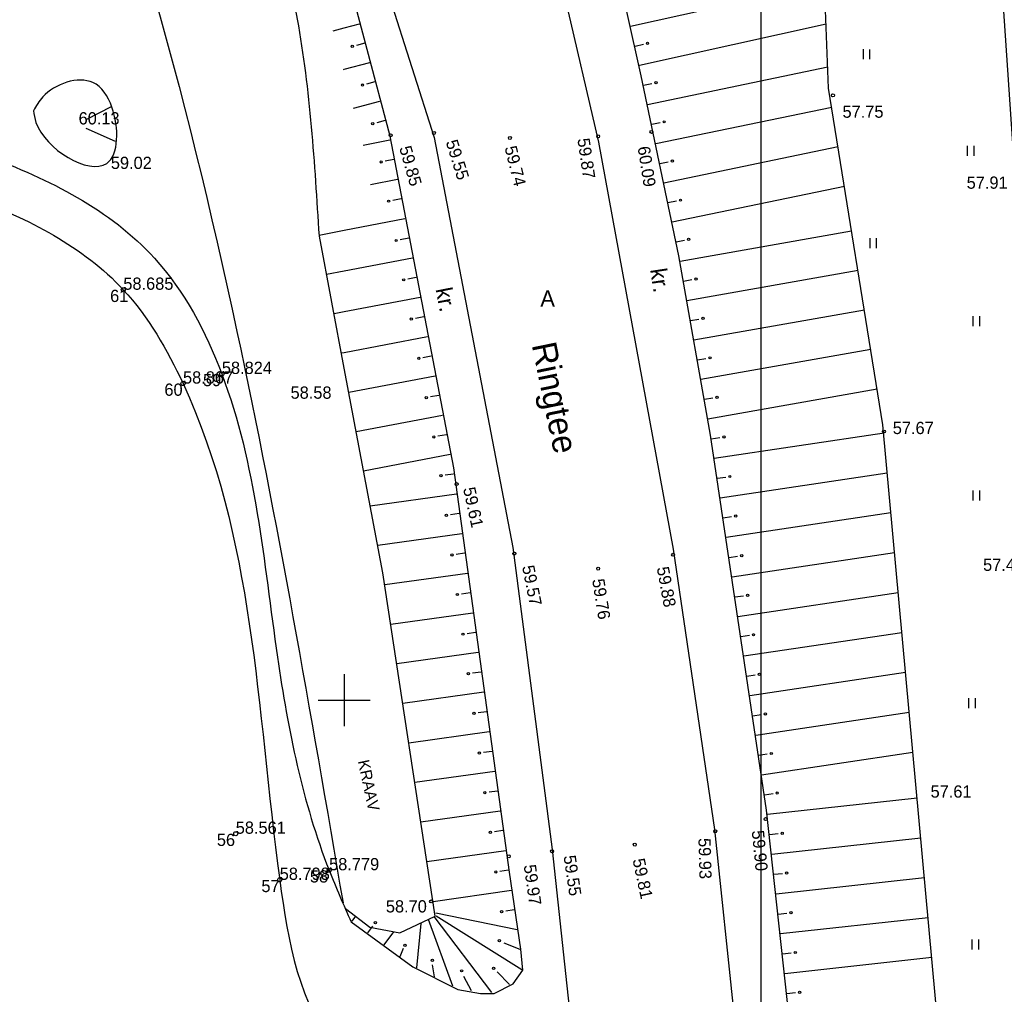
# Model space of a CAD drawing. Extents: x 9156 to 9809, y 2728 to 4000.
# Drawn here: x 9230.1 to 9290.4, y 3632 to 3691.7 of the extents above; entities that cross this region are included whole.
import ezdxf

# ---------------------------------------------------------------- set-up
doc = ezdxf.new("R2010")
doc.units = 0
doc.layers.add('Level 54', color=7, linetype='Continuous')
doc.layers.add('Level 63', color=7, linetype='Continuous')

msp = doc.modelspace()

# ---------------------------------------------------------------- linework, layer by layer
at = {"layer": 'Level 54'}
for p, q in [((9265.589, 3684.178), (9262.725, 3696.473)), ((9279.408, 3693.912), (9267.541, 3691.269)), ((9252.647, 3693.428), (9255.511, 3684.465)), ((9250, 3691.186), (9250.935, 3691.433)), ((9279.509, 3691.423), (9268.073, 3688.877)), ((9249.316, 3691.006), (9250, 3691.186)), ((9251.247, 3690.248), (9250.739, 3690.114)), ((9267.807, 3690.073), (9268.32, 3690.187)), ((9281.776, 3689.881), (9281.776, 3689.261)), ((9282.181, 3689.87), (9282.181, 3689.261)), ((9250, 3688.652), (9251.56, 3689.062)), ((9249.941, 3688.636), (9250, 3688.652)), ((9279.616, 3688.771), (9268.581, 3686.479)), ((9251.872, 3687.877), (9251.363, 3687.743)), ((9268.331, 3687.679), (9268.846, 3687.786)), ((9250.565, 3686.266), (9252.184, 3686.692)), ((9234.228, 3685.586), (9235.745, 3686.368)), ((9279.858, 3686.318), (9269.079, 3684.079)), ((9252.496, 3685.507), (9251.988, 3685.373)), ((9268.83, 3685.279), (9269.345, 3685.386)), ((9234.165, 3685.037), (9235.956, 3684.256)), ((9251.149, 3684.003), (9252.793, 3684.318)), ((9255.511, 3684.465), (9260.322, 3659.355)), ((9270.172, 3659.243), (9265.589, 3684.178)), ((9280.248, 3683.896), (9269.578, 3681.679)), ((9288.165, 3683.966), (9288.165, 3683.346)), ((9288.571, 3683.954), (9288.571, 3683.346)), ((9253.024, 3683.115), (9252.507, 3683.016)), ((9269.328, 3682.879), (9269.843, 3682.986)), ((9251.61, 3681.596), (9253.255, 3681.911)), ((9280.638, 3681.473), (9270.076, 3679.279)), ((9253.485, 3680.707), (9252.969, 3680.608)), ((9269.827, 3680.479), (9270.342, 3680.586)), ((9250, 3678.792), (9253.716, 3679.504)), ((9248.459, 3678.496), (9250, 3678.792)), ((9281.078, 3678.739), (9270.564, 3676.877)), ((9250, 3670.328), (9248.471, 3678.435)), ((9253.946, 3678.3), (9253.43, 3678.201)), ((9270.325, 3678.079), (9270.84, 3678.186)), ((9282.183, 3678.307), (9282.183, 3677.687)), ((9282.588, 3678.296), (9282.588, 3677.687)), ((9250, 3676.296), (9254.177, 3677.096)), ((9248.913, 3676.088), (9250, 3676.296)), ((9254.408, 3675.893), (9253.891, 3675.794)), ((9270.778, 3675.67), (9271.296, 3675.762)), ((9281.468, 3676.319), (9270.992, 3674.464)), ((9250, 3673.8), (9254.638, 3674.689)), ((9249.368, 3673.679), (9250, 3673.8)), ((9254.869, 3673.485), (9254.353, 3673.386)), ((9271.205, 3673.257), (9271.723, 3673.348)), ((9281.858, 3673.898), (9271.419, 3672.05)), ((9288.505, 3673.534), (9288.505, 3672.914)), ((9288.91, 3673.523), (9288.91, 3672.914)), ((9250, 3671.304), (9255.1, 3672.282)), ((9249.822, 3671.27), (9250, 3671.304)), ((9255.33, 3671.078), (9254.814, 3670.979)), ((9271.633, 3670.843), (9272.15, 3670.935)), ((9282.248, 3671.478), (9271.846, 3669.636)), ((9252.363, 3657.799), (9250, 3670.328)), ((9250.277, 3668.862), (9255.561, 3669.874)), ((9255.792, 3668.671), (9255.275, 3668.572)), ((9272.06, 3668.43), (9272.578, 3668.521)), ((9282.637, 3669.058), (9272.274, 3667.223)), ((9250.731, 3666.453), (9256.022, 3667.467)), ((9256.253, 3666.263), (9255.737, 3666.164)), ((9272.481, 3666.015), (9273.001, 3666.093)), ((9283.072, 3666.36), (9272.662, 3664.803)), ((9251.185, 3664.044), (9256.484, 3665.06)), ((9256.695, 3663.853), (9256.175, 3663.781)), ((9272.844, 3663.591), (9273.364, 3663.669)), ((9283.261, 3663.91), (9273.025, 3662.379)), ((9251.588, 3661.909), (9256.863, 3662.639)), ((9288.505, 3662.852), (9288.505, 3662.232)), ((9288.91, 3662.841), (9288.91, 3662.232)), ((9257.031, 3661.425), (9256.511, 3661.353)), ((9283.486, 3661.465), (9273.388, 3659.955)), ((9273.206, 3661.167), (9273.726, 3661.244)), ((9252.043, 3659.497), (9257.199, 3660.211)), ((9257.368, 3658.997), (9256.847, 3658.925)), ((9260.322, 3659.355), (9262.728, 3640.855)), ((9272.689, 3642.079), (9270.172, 3659.243)), ((9283.71, 3659.02), (9273.75, 3657.53)), ((9273.569, 3658.742), (9274.089, 3658.82)), ((9255.572, 3636.771), (9252.363, 3657.799)), ((9252.473, 3657.082), (9257.536, 3657.783)), ((9257.704, 3656.569), (9257.183, 3656.497)), ((9283.934, 3656.575), (9274.113, 3655.106)), ((9273.931, 3656.318), (9274.451, 3656.396)), ((9252.843, 3654.659), (9257.872, 3655.355)), ((9258.04, 3654.141), (9257.519, 3654.069)), ((9284.159, 3654.13), (9274.475, 3652.682)), ((9274.294, 3653.894), (9274.814, 3653.972)), ((9253.212, 3652.235), (9258.208, 3652.927)), ((9258.376, 3651.713), (9257.855, 3651.641)), ((9284.383, 3651.686), (9274.838, 3650.258)), ((9250, 3651.593), (9250, 3648.407)), ((9250, 3651.593), (9250, 3648.407)), ((9250, 3651.593), (9250, 3648.407)), ((9250, 3651.593), (9250, 3648.407)), ((9250, 3651.25), (9250, 3648.75)), ((9274.657, 3651.47), (9275.177, 3651.548)), ((9253.582, 3649.812), (9258.544, 3650.499)), ((9248.407, 3650), (9250, 3650)), ((9248.407, 3650), (9250, 3650)), ((9248.75, 3650), (9251.25, 3650)), ((9250, 3650), (9251.593, 3650)), ((9250, 3650), (9251.593, 3650)), ((9288.233, 3650.122), (9288.233, 3649.502)), ((9288.638, 3650.111), (9288.638, 3649.502)), ((9258.712, 3649.285), (9258.191, 3649.213)), ((9284.608, 3649.241), (9275.2, 3647.834)), ((9275.019, 3649.046), (9275.539, 3649.124)), ((9253.952, 3647.389), (9258.88, 3648.071)), ((9259.048, 3646.857), (9258.527, 3646.785)), ((9284.832, 3646.796), (9275.563, 3645.41)), ((9275.382, 3646.622), (9275.902, 3646.699)), ((9254.321, 3644.965), (9259.216, 3645.643)), ((9259.384, 3644.429), (9258.863, 3644.357)), ((9275.744, 3644.197), (9276.264, 3644.275)), ((9285.09, 3643.986), (9275.914, 3642.984)), ((9254.691, 3642.542), (9259.552, 3643.215)), ((9259.72, 3642.001), (9259.199, 3641.929)), ((9278.071, 3591.482), (9272.689, 3642.079)), ((9276.047, 3641.766), (9276.57, 3641.823)), ((9285.314, 3641.544), (9276.18, 3640.547)), ((9255.061, 3640.119), (9259.888, 3640.787)), ((9262.728, 3640.855), (9267.882, 3592.77)), ((9260.056, 3639.573), (9259.535, 3639.501)), ((9276.313, 3639.329), (9276.836, 3639.386)), ((9285.538, 3639.103), (9276.446, 3638.111)), ((9255.436, 3637.66), (9260.232, 3638.36)), ((9250.072, 3637.23), (9251.561, 3636.081)), ((9260.409, 3637.147), (9259.889, 3637.071)), ((9250.676, 3636.764), (9250.45, 3636.455)), ((9253.395, 3635.736), (9255.572, 3636.771)), ((9255.146, 3636.572), (9256.621, 3632.498)), ((9255.49, 3636.744), (9259.01, 3632.088)), ((9255.605, 3636.974), (9260.586, 3635.935)), ((9255.633, 3636.773), (9260.873, 3633.501)), ((9276.579, 3636.892), (9277.102, 3636.949)), ((9285.763, 3636.662), (9276.712, 3635.674)), ((9251.44, 3635.732), (9251.75, 3636.157)), ((9251.561, 3636.081), (9253.395, 3635.736)), ((9254.688, 3636.313), (9254.43, 3633.597)), ((9253.012, 3635.808), (9252.43, 3635.01)), ((9288.436, 3635.342), (9288.436, 3634.722)), ((9288.842, 3635.331), (9288.842, 3634.722)), ((9253.42, 3634.288), (9253.628, 3634.791)), ((9260.762, 3634.722), (9259.787, 3635.107)), ((9276.845, 3634.456), (9277.368, 3634.513)), ((9285.987, 3634.221), (9276.978, 3633.237)), ((9255.525, 3633.048), (9255.404, 3633.785)), ((9257.792, 3632.182), (9257.323, 3633.067)), ((9260.121, 3632.571), (9259.357, 3633.354)), ((9277.111, 3632.019), (9277.634, 3632.076))]:
    msp.add_line(p, q, dxfattribs=at)
for points in [[(9250, 3738.614), (9253.398, 3731.987), (9257.522, 3722.336), (9261.761, 3711.307), (9265.539, 3700.09), (9268.174, 3688.256), (9270.465, 3677.226), (9272.41, 3666.239), (9275.847, 3643.259), (9278.136, 3622.295), (9281, 3595.752), (9283.628, 3570.325), (9285.461, 3545.046), (9287.293, 3525.67), (9289.24, 3507.056), (9289.458, 3500)], [(9289.521, 3722.865), (9289.636, 3711.949), (9290.094, 3696.436), (9293.302, 3649.242), (9295.59, 3619.198), (9296.851, 3602.192), (9300.163, 3556.342), (9301.424, 3542.094), (9302.684, 3538.991), (9304.632, 3528.075), (9306.915, 3513.758), (9308.634, 3504.221), (9309.025, 3500)], [(9298.789, 3500), (9298.217, 3515.72), (9298.103, 3526.407), (9296.155, 3540.196), (9294.785, 3549.211), (9292.952, 3569.435), (9290.202, 3589.084), (9286.767, 3619.468), (9285.736, 3621.307), (9285.048, 3622.915), (9284.705, 3624.754), (9285.736, 3627.512), (9286.423, 3629.465), (9282.989, 3666.871), (9279.667, 3687.502), (9279.324, 3696.006), (9278.522, 3701.406), (9275.886, 3702.9), (9273.137, 3704.049)], [(9250.418, 3636.41), (9254.202, 3633.65), (9256.963, 3632.265), (9258.351, 3632.033), (9259.17, 3632.033), (9260.34, 3632.62), (9260.932, 3633.452), (9260.816, 3634.737), (9260.128, 3639.45), (9256.699, 3664.227), (9252.804, 3684.55), (9250, 3695.198)]]:
    msp.add_lwpolyline(points, dxfattribs=at)
for centre, radius in [((9268.571, 3690.236), 0.0683), ((9250.49, 3690.056), 0.0683), ((9269.098, 3687.83), 0.0683), ((9251.114, 3687.685), 0.0683), ((9279.936, 3687.055), 0.0909), ((9251.739, 3685.315), 0.0683), ((9269.596, 3685.43), 0.0683), ((9255.489, 3684.748), 0.0909), ((9268.813, 3684.816), 0.0909), ((9252.838, 3684.612), 0.0909), ((9260.146, 3684.441), 0.0909), ((9265.55, 3684.544), 0.0909), ((9252.255, 3682.975), 0.0683), ((9270.095, 3683.031), 0.0683), ((9252.716, 3680.568), 0.0683), ((9270.593, 3680.631), 0.0683), ((9253.178, 3678.16), 0.0683), ((9271.092, 3678.231), 0.0683), ((9253.639, 3675.753), 0.0683), ((9271.549, 3675.799), 0.0683), ((9236.462, 3675.142), 0.125), ((9254.1, 3673.346), 0.0683), ((9271.976, 3673.386), 0.0683), ((9254.562, 3670.938), 0.0683), ((9272.403, 3670.972), 0.0683), ((9242.498, 3669.984), 0.125), ((9240.118, 3669.396), 0.125), ((9255.023, 3668.531), 0.0683), ((9272.831, 3668.558), 0.0683), ((9255.484, 3666.124), 0.0683), ((9273.255, 3666.123), 0.0683), ((9283.056, 3666.453), 0.0909), ((9255.92, 3663.753), 0.0683), ((9273.617, 3663.699), 0.0683), ((9256.882, 3663.237), 0.0909), ((9256.256, 3661.325), 0.0683), ((9273.98, 3661.275), 0.0683), ((9256.593, 3658.897), 0.0683), ((9260.417, 3658.976), 0.0909), ((9270.138, 3658.908), 0.0909), ((9274.343, 3658.851), 0.0683), ((9265.55, 3658.055), 0.0909), ((9256.929, 3656.469), 0.0683), ((9274.705, 3656.426), 0.0683), ((9257.265, 3654.041), 0.0683), ((9275.068, 3654.002), 0.0683), ((9257.601, 3651.613), 0.0683), ((9275.43, 3651.578), 0.0683), ((9257.937, 3649.185), 0.0683), ((9275.793, 3649.154), 0.0683), ((9258.273, 3646.757), 0.0683), ((9276.156, 3646.73), 0.0683), ((9258.609, 3644.329), 0.0683), ((9276.518, 3644.306), 0.0683), ((9275.809, 3642.712), 0.0909), ((9258.945, 3641.901), 0.0683), ((9272.721, 3641.962), 0.0909), ((9243.348, 3641.811), 0.125), ((9276.825, 3641.843), 0.0683), ((9262.728, 3640.735), 0.0909), ((9267.793, 3641.144), 0.0909), ((9260.077, 3640.428), 0.0909), ((9249.068, 3639.574), 0.125), ((9259.281, 3639.473), 0.0683), ((9246.042, 3638.986), 0.125), ((9277.091, 3639.406), 0.0683), ((9255.318, 3637.667), 0.0909), ((9259.635, 3637.042), 0.0683), ((9277.357, 3636.97), 0.0683), ((9251.906, 3636.359), 0.0683), ((9259.497, 3635.262), 0.0683), ((9253.715, 3634.972), 0.0683), ((9255.395, 3634.059), 0.0683), ((9277.623, 3634.533), 0.0683), ((9259.147, 3633.56), 0.0683), ((9257.184, 3633.411), 0.0683), ((9277.889, 3632.096), 0.0683)]:
    msp.add_circle(centre, radius, dxfattribs=at)
for points in [[(9213.624, 3749.588), (9230.716, 3715.459), (9243.421, 3672.591), (9249.922, 3637.572)], [(9248.471, 3678.435), (9247.131, 3691.729), (9237.223, 3718.574), (9221.358, 3749.893)], [(9171.373, 3737.784), (9171.217, 3714.852), (9173.592, 3702.06), (9185.483, 3685.771), (9201.99, 3683.944), (9227.179, 3680.783), (9236.462, 3675.142), (9240.118, 3669.396), (9246.042, 3638.986), (9249.576, 3628.506), (9250.19, 3627.811)], [(9176.163, 3735.676), (9174.543, 3713.881), (9177.243, 3702.762), (9186.786, 3688.435), (9202.273, 3686.639), (9228.076, 3683.334), (9238.363, 3677.083), (9242.498, 3669.984), (9245.905, 3652.634), (9249.068, 3639.574), (9250.418, 3636.41)], [(9230.953, 3686.11), (9231.531, 3686.959), (9234.599, 3687.838), (9235.766, 3686.326), (9235.444, 3682.881), (9231.109, 3685.396), (9230.953, 3686.11)]]:
    msp.add_spline(points, degree=3, dxfattribs=at)
at = {"layer": 'Level 63'}
msp.add_lwpolyline([(9275.527, 3966.797), (9801.617, 3966.797), (9801.617, 3329.636), (9275.527, 3329.636)], close=True, dxfattribs=at)

# ---------------------------------------------------------------- texts
at = {"layer": 'Level 54'}
for s, height, p in [('60.13', 0.75, (9233.722, 3685.272)), ('57.75', 0.75, (9280.519, 3685.681)), ('59.02', 0.75, (9235.697, 3682.543)), ('57.91', 0.75, (9288.125, 3681.331)), ('58.685', 0.75, (9236.462, 3675.142)), ('61', 0.75, (9235.653, 3674.392)), ('A', 1, (9262.009, 3674.11)), ('58.824', 0.75, (9242.498, 3669.984)), ('58.867', 0.75, (9240.118, 3669.396)), ('59', 0.75, (9241.341, 3669.234)), ('60', 0.75, (9238.978, 3668.646)), ('58.58', 0.75, (9246.707, 3668.466)), ('57.67', 0.75, (9283.598, 3666.3)), ('57.48', 0.75, (9289.13, 3657.915)), ('57.61', 0.75, (9285.913, 3644.024)), ('58.561', 0.75, (9243.348, 3641.811)), ('56', 0.75, (9242.191, 3641.061)), ('58.779', 0.75, (9249.068, 3639.574)), ('58.798', 0.75, (9246.042, 3638.986)), ('58', 0.75, (9247.893, 3638.824)), ('57', 0.75, (9244.92, 3638.236)), ('58.70', 0.75, (9252.545, 3636.988))]:
    msp.add_text(s, height=height, dxfattribs=at).set_placement(p)
for s, height, rotation, p in [('59.55', 0.75, 287.30695, (9256.203, 3684.198)), ('59.87', 0.75, 278.34233, (9264.276, 3684.376)), ('59.85', 0.75, 285.90166, (9253.357, 3683.837)), ('59.74', 0.75, 283.99828, (9259.81, 3683.855)), ('60.09', 0.75, 278.85572, (9267.966, 3683.879)), ('kr.', 1, 278.64843, (9268.731, 3676.384)), ('kr.', 1, 281.07302, (9255.582, 3675.179)), ('Ringtee', 1.5, 281.60909, (9261.475, 3671.773)), ('59.61', 0.75, 282.23048, (9257.271, 3662.961)), ('59.57', 0.75, 281.27841, (9260.884, 3658.183)), ('59.88', 0.75, 280.50987, (9269.133, 3658.105)), ('59.76', 0.75, 279.06485, (9265.177, 3657.375)), ('KRAAV', 0.7, 282.06527, (9250.822, 3646.261)), ('59.90', 0.75, 275.69422, (9274.956, 3641.987)), ('59.93', 0.75, 271.50308, (9271.69, 3641.538)), ('59.55', 0.75, 278.40334, (9263.424, 3640.441)), ('59.81', 0.75, 281.97801, (9267.655, 3640.216)), ('59.97', 0.75, 278.10717, (9260.986, 3639.871))]:
    msp.add_text(s, height=height, rotation=rotation, dxfattribs=at).set_placement(p)

doc.saveas('drawing.dxf')
